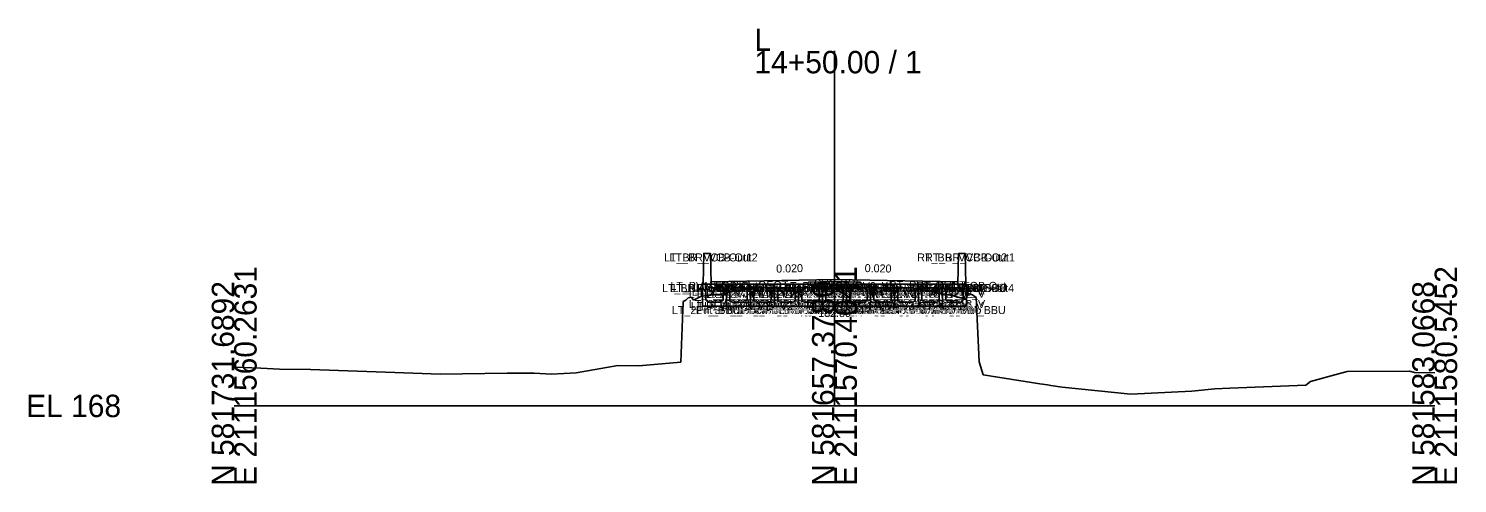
# Model space of a CAD drawing. Extents: x -26 to 3453, y -333 to 9539.
# Drawn here: x -25.7 to 152.8, y 4490.3 to 4547.2 of the extents above; entities that cross this region are included whole.
import ezdxf

# ---------------------------------------------------------------- set-up
doc = ezdxf.new("R2010")
doc.units = 0
for name, color, linetype in [('Default', 7, 'Continuous'), ('Exist Cross Section Cell', 7, 'Continuous'), ('Exist XS Center Line Elevation Label', 7, 'Continuous'), ('Exist XS Ground Line', 7, 'Continuous'), ('Prop CMT Concrete Structures', 7, 'Continuous'), ('Prop CMT Pvmt Course 1', 7, 'Continuous'), ('Prop XS SE Text', 7, 'Continuous'), ('Scratch_Level_0', 7, 'Continuous')]:
    doc.layers.add(name, color=color, linetype=linetype)

msp = doc.modelspace()

# ---------------------------------------------------------------- linework, layer by layer
at = {"layer": 'Exist Cross Section Cell'}
for p, q in [((75, 4500), (75, 4544.39)), ((0, 4500), (75, 4500)), ((75, 4500), (150, 4500))]:
    msp.add_line(p, q, dxfattribs=at)
at = {"layer": 'Exist XS Ground Line'}
for p, q in [((56.41, 4513.23), (56.72, 4513.53)), ((56.72, 4513.53), (57.12, 4513.62)), ((57.12, 4513.62), (57.37, 4513.23)), ((57.37, 4513.23), (58.4, 4513.74)), ((58.4, 4513.74), (61.09, 4514.02)), ((61.09, 4514.02), (63.76, 4514.64)), ((63.76, 4514.64), (64.81, 4514.76)), ((64.81, 4514.76), (74.33, 4514.8)), ((74.33, 4514.8), (74.8, 4514.8)), ((74.8, 4514.8), (84.18, 4514.76)), ((84.18, 4514.76), (84.63, 4514.75)), ((84.63, 4514.75), (89.82, 4513.76)), ((89.82, 4513.76), (91.42, 4513.36)), ((91.42, 4513.36), (91.7, 4514.08)), ((91.7, 4514.08), (92.27, 4513.9)), ((92.27, 4513.9), (92.69, 4513.56)), ((92.69, 4513.56), (93.1, 4505.5)), ((55.82, 4505.48), (56.08, 4513.06)), ((56.08, 4513.06), (56.41, 4513.23)), ((0, 4504.84), (3.33, 4504.71)), ((3.33, 4504.71), (5.64, 4504.61)), ((5.64, 4504.61), (9.53, 4504.57)), ((9.53, 4504.57), (20.08, 4504.18)), ((42.72, 4504.14), (47.94, 4505.05)), ((47.94, 4505.05), (50.56, 4505.02)), ((50.56, 4505.02), (55.82, 4505.48)), ((93.1, 4505.5), (93.6, 4503.88)), ((20.08, 4504.18), (25.72, 4503.96)), ((25.72, 4503.96), (34.11, 4504.08)), ((34.11, 4504.08), (37.46, 4504.08)), ((37.46, 4504.08), (39.64, 4503.96)), ((39.64, 4503.96), (42.72, 4504.14)), ((93.6, 4503.88), (100.66, 4502.78)), ((100.66, 4502.78), (101.63, 4502.63)), ((101.63, 4502.63), (102.05, 4502.54)), ((124.4, 4502.23), (133.89, 4502.6)), ((133.89, 4502.6), (134.47, 4503.06)), ((134.47, 4503.06), (137.99, 4504.03)), ((137.99, 4504.03), (139.05, 4504.31)), ((139.05, 4504.31), (146.86, 4504.33)), ((146.86, 4504.33), (147.47, 4504.2)), ((147.47, 4504.2), (150, 4504.12)), ((102.05, 4502.54), (103.45, 4502.36)), ((103.45, 4502.36), (112.03, 4501.49)), ((112.03, 4501.49), (119.67, 4501.83)), ((119.67, 4501.83), (122.53, 4502.15)), ((122.53, 4502.15), (124.4, 4502.23))]:
    msp.add_line(p, q, dxfattribs=at)
at = {"layer": 'Prop CMT Concrete Structures'}
for points in [[(59.58, 4515.24), (59.5, 4519.07), (58.66, 4519.07), (58.58, 4515.24)], [(90.42, 4515.24), (90.5, 4519.07), (91.33, 4519.07), (91.42, 4515.24)], [(61.5, 4515.24), (58.5, 4515.24)], [(58.5, 4515.24), (58.5, 4512.49)], [(58.58, 4515.24), (59.58, 4515.24)], [(64.5, 4515.24), (61.5, 4515.24)], [(61.5, 4515.24), (61.5, 4512.49)], [(61.5, 4512.49), (61.5, 4515.24)], [(67.5, 4515.24), (64.5, 4515.24)], [(64.5, 4515.24), (64.5, 4512.49)], [(64.5, 4512.49), (64.5, 4515.24)], [(70.5, 4515.24), (67.5, 4515.24)], [(67.5, 4515.24), (67.5, 4512.49)], [(67.5, 4512.49), (67.5, 4515.24)], [(70.5, 4512.49), (70.5, 4515.24)], [(73.51, 4515.24), (70.5, 4515.24)], [(70.5, 4515.24), (70.5, 4512.49)], [(75, 4515.24), (73.51, 4515.24)], [(73.51, 4515.24), (73.51, 4512.49)], [(73.51, 4512.49), (73.51, 4515.24)], [(75, 4515.24), (76.49, 4515.24)], [(76.49, 4515.24), (76.49, 4512.49)], [(76.5, 4515.24), (79.5, 4515.24)], [(76.5, 4512.49), (76.5, 4515.24)], [(79.5, 4515.24), (82.5, 4515.24)], [(79.5, 4512.49), (79.5, 4515.24)], [(79.5, 4515.24), (79.5, 4512.49)], [(82.5, 4515.24), (82.5, 4512.49)], [(82.5, 4515.24), (85.5, 4515.24)], [(82.5, 4512.49), (82.5, 4515.24)], [(85.5, 4515.24), (85.5, 4512.49)], [(85.5, 4515.24), (88.5, 4515.24)], [(85.5, 4512.49), (85.5, 4515.24)], [(88.5, 4515.24), (88.5, 4512.49)], [(88.5, 4515.24), (91.5, 4515.24)], [(88.5, 4512.49), (88.5, 4515.24)], [(91.42, 4515.24), (90.42, 4515.24)], [(91.5, 4515.24), (91.5, 4512.49)], [(58.92, 4514.53), (59.17, 4514.78)], [(58.92, 4513.24), (58.92, 4514.53)], [(59.17, 4514.78), (60.83, 4514.78), (61.08, 4514.53)], [(61.08, 4514.53), (61.08, 4513.24)], [(61.92, 4514.53), (62.17, 4514.78)], [(61.92, 4513.24), (61.92, 4514.53)], [(62.17, 4514.78), (63.83, 4514.78), (64.08, 4514.53)], [(64.08, 4514.53), (64.08, 4513.24)], [(64.92, 4514.53), (65.17, 4514.78)], [(64.92, 4513.24), (64.92, 4514.53)], [(65.17, 4514.78), (66.83, 4514.78), (67.08, 4514.53)], [(67.08, 4514.53), (67.08, 4513.24)], [(67.92, 4514.53), (68.17, 4514.78)], [(67.92, 4513.24), (67.92, 4514.53)], [(68.17, 4514.78), (69.83, 4514.78), (70.08, 4514.53)], [(70.08, 4514.53), (70.08, 4513.24)], [(70.92, 4514.53), (71.17, 4514.78)], [(70.92, 4513.24), (70.92, 4514.53)], [(71.17, 4514.78), (72.84, 4514.78), (73.09, 4514.53)], [(73.09, 4514.53), (73.09, 4513.24)], [(73.93, 4514.53), (74.18, 4514.78), (75, 4514.78)], [(73.93, 4513.24), (73.93, 4514.53)], [(76.07, 4514.53), (75.82, 4514.78), (75, 4514.78)], [(76.07, 4513.24), (76.07, 4514.53)], [(78.83, 4514.78), (77.17, 4514.78), (76.92, 4514.53)], [(76.92, 4514.53), (76.92, 4513.24)], [(79.08, 4514.53), (78.83, 4514.78)], [(79.08, 4513.24), (79.08, 4514.53)], [(81.83, 4514.78), (80.17, 4514.78), (79.92, 4514.53)], [(79.92, 4514.53), (79.92, 4513.24)], [(82.08, 4514.53), (81.83, 4514.78)], [(82.08, 4513.24), (82.08, 4514.53)], [(84.83, 4514.78), (83.17, 4514.78), (82.92, 4514.53)], [(82.92, 4514.53), (82.92, 4513.24)], [(85.08, 4514.53), (84.83, 4514.78)], [(85.08, 4513.24), (85.08, 4514.53)], [(87.83, 4514.78), (86.17, 4514.78), (85.92, 4514.53)], [(85.92, 4514.53), (85.92, 4513.24)], [(88.08, 4514.53), (87.83, 4514.78)], [(88.08, 4513.24), (88.08, 4514.53)], [(90.83, 4514.78), (89.17, 4514.78), (88.92, 4514.53)], [(88.92, 4514.53), (88.92, 4513.24)], [(91.08, 4514.53), (90.83, 4514.78)], [(91.08, 4513.24), (91.08, 4514.53)], [(58.5, 4512.49), (61.5, 4512.49)], [(61.08, 4513.24), (60.83, 4512.99), (59.17, 4512.99), (58.92, 4513.24)], [(61.5, 4512.49), (64.5, 4512.49)], [(64.08, 4513.24), (63.83, 4512.99), (62.17, 4512.99), (61.92, 4513.24)], [(64.5, 4512.49), (67.5, 4512.49)], [(67.08, 4513.24), (66.83, 4512.99), (65.17, 4512.99), (64.92, 4513.24)], [(67.5, 4512.49), (70.5, 4512.49)], [(70.08, 4513.24), (69.83, 4512.99), (68.17, 4512.99), (67.92, 4513.24)], [(70.5, 4512.49), (73.51, 4512.49)], [(73.09, 4513.24), (72.84, 4512.99), (71.17, 4512.99), (70.92, 4513.24)], [(73.51, 4512.49), (75, 4512.49)], [(75, 4512.99), (74.18, 4512.99), (73.93, 4513.24)], [(75, 4512.99), (75.82, 4512.99), (76.07, 4513.24)], [(76.49, 4512.49), (75, 4512.49)], [(79.5, 4512.49), (76.5, 4512.49)], [(76.92, 4513.24), (77.17, 4512.99), (78.83, 4512.99), (79.08, 4513.24)], [(82.5, 4512.49), (79.5, 4512.49)], [(79.92, 4513.24), (80.17, 4512.99), (81.83, 4512.99), (82.08, 4513.24)], [(85.5, 4512.49), (82.5, 4512.49)], [(82.92, 4513.24), (83.17, 4512.99), (84.83, 4512.99), (85.08, 4513.24)], [(88.5, 4512.49), (85.5, 4512.49)], [(85.92, 4513.24), (86.17, 4512.99), (87.83, 4512.99), (88.08, 4513.24)], [(91.5, 4512.49), (88.5, 4512.49)], [(88.92, 4513.24), (89.17, 4512.99), (90.83, 4512.99), (91.08, 4513.24)]]:
    msp.add_lwpolyline(points, dxfattribs=at)
at = {"layer": 'Prop CMT Pvmt Course 1'}
for points in [[(75, 4515.82), (64, 4515.6), (59.57, 4515.51)], [(59.57, 4515.51), (59.58, 4515.24), (61.34, 4515.24), (71.5, 4515.24), (71.76, 4515.49), (75, 4515.57)], [(75, 4515.57), (75, 4515.82)], [(75, 4515.82), (86, 4515.6), (90.42, 4515.51)], [(75, 4515.57), (75, 4515.82)], [(90.42, 4515.51), (90.42, 4515.24), (88.66, 4515.24), (78.5, 4515.24), (78.24, 4515.49), (75, 4515.57)]]:
    msp.add_lwpolyline(points, dxfattribs=at)

# ---------------------------------------------------------------- texts
at = {"layer": 'Default'}
msp.add_text('-', height=0.0001, dxfattribs=at).set_placement((0, 4500))
at = {"layer": 'Exist Cross Section Cell'}
for s, p in [('L', (65, 4544.39)), ('14+50.00 / 1', (65, 4541.59)), ('EL 168', (-26, 4498.6))]:
    msp.add_text(s, height=2.8, dxfattribs=at).set_placement(p)
for s, p in [('E 2111560.2631', (2.8, 4490)), ('E 2111570.4041', (77.8, 4490)), ('E 2111580.5452', (152.8, 4490)), ('N 581731.6892', (0, 4490)), ('N 581657.3780', (75, 4490)), ('N 581583.0668', (150, 4490))]:
    msp.add_text(s, height=2.8, rotation=90, dxfattribs=at).set_placement(p)
at = {"layer": 'Exist XS Center Line Elevation Label'}
msp.add_text('182.80', height=1, dxfattribs=at).set_placement((72.97, 4511.12))
at = {"layer": 'Prop XS SE Text'}
for rotation, p in [(1.1458, (67.73, 4516.67)), (358.8542, (78.77, 4516.74))]:
    msp.add_text('0.020', height=1, rotation=rotation, dxfattribs=at).set_placement(p)
at = {"layer": 'Scratch_Level_0'}
for s, p in [('LT_BR_VCB-Out1', (53.71, 4518.07)), ('LT_BR_VCB-Out2', (54.4, 4518.07)), ('RT_BR_VCB-Out2', (85.35, 4518.07)), ('RT_BR_VCB-Out1', (86.32, 4518.07)), ('LT_BR_VCB-Out4', (53.45, 4514.24)), ('LT_BR_VCB-Out3', (54.47, 4514.24)), ('LT_PV1_FOB-Out', (54.5, 4514.51)), ('LT_1Pnt_BBU', (54.81, 4514.24)), ('LT_4Pnt_BBU', (57.69, 4514.24)), ('LT_PV1_Tent', (57.75, 4514.24)), ('LT_PV1_OEOT', (59.87, 4514.6)), ('LT_4Pnt_BBU1', (60.45, 4514.24)), ('LT_4Pnt_BBU2', (63.31, 4514.24)), ('LT_4Pnt_BBU3', (66.29, 4514.24)), ('LT_PV2_W', (68.7, 4514.49)), ('LT_BR_W', (68.85, 4514.24)), ('LT_4Pnt_BBU5', (69.3, 4514.24)), ('LT_1Pnt_BBU1', (69.58, 4514.24)), ('RT_4Pnt_BBU5', (72.23, 4514.24)), ('PV2_PGL', (72.35, 4514.57)), ('PV1_PGL', (72.47, 4514.82)), ('RT_1Pnt_BBU1', (72.5, 4514.24)), ('BR_PGL', (72.75, 4514.24)), ('RT_PV2_W', (75.12, 4514.49)), ('RT_4Pnt_BBU3', (75.23, 4514.24)), ('RT_BR_W', (75.78, 4514.24)), ('RT_4Pnt_BBU2', (78.25, 4514.24)), ('RT_4Pnt_BBU1', (81.39, 4514.24)), ('RT_PV1_OEOT', (81.81, 4514.6)), ('RT_4Pnt_BBU', (84.63, 4514.24)), ('RT_PV1_Tent', (85.01, 4514.24)), ('RT_BR_VCB-Out3', (85.25, 4514.24)), ('RT_PV1_FOB-Out', (85.29, 4514.51)), ('RT_BR_VCB-Out4', (86.23, 4514.24)), ('RT_1Pnt_BBU', (87.75, 4514.24)), ('LT_2_V', (56.81, 4513.53)), ('LT_1_V', (57.18, 4513.78)), ('LT_8_V', (58.73, 4513.78)), ('LT_7_V', (58.98, 4513.53)), ('LT_2_V1', (59.64, 4513.53)), ('LT_1_V1', (60.01, 4513.78)), ('LT_8_V1', (61.56, 4513.78)), ('LT_7_V1', (61.81, 4513.53)), ('LT_2_V2', (62.49, 4513.53)), ('LT_1_V2', (62.86, 4513.78)), ('LT_8_V2', (64.41, 4513.78)), ('LT_7_V2', (64.66, 4513.53)), ('LT_2_V3', (65.48, 4513.53)), ('LT_1_V3', (65.85, 4513.78)), ('LT_8_V3', (67.39, 4513.78)), ('LT_7_V3', (67.64, 4513.53)), ('LT_2_V6', (68.47, 4513.53)), ('LT_1_V6', (68.83, 4513.78)), ('LT_8_V5', (70.4, 4513.78)), ('LT_7_V5', (70.65, 4513.53)), ('LT_2_V4', (71.47, 4513.53)), ('LT_1_V4', (71.84, 4513.78)), ('RT_1_V4', (73.43, 4513.78)), ('6_V4', (73.51, 4513.78)), ('RT_2_V4', (73.56, 4513.53)), ('RT_7_V5', (74.41, 4513.53)), ('RT_8_V5', (74.66, 4513.78)), ('RT_1_V6', (76.44, 4513.78)), ('RT_2_V6', (76.57, 4513.53)), ('RT_7_V3', (77.42, 4513.53)), ('RT_8_V3', (77.67, 4513.78)), ('RT_1_V3', (79.45, 4513.78)), ('RT_2_V3', (79.59, 4513.53)), ('RT_7_V2', (80.43, 4513.53)), ('RT_8_V2', (80.68, 4513.78)), ('RT_1_V2', (82.47, 4513.78)), ('RT_2_V2', (82.6, 4513.53)), ('RT_7_V1', (83.58, 4513.53)), ('RT_8_V1', (83.83, 4513.78)), ('RT_1_V1', (85.62, 4513.78)), ('RT_2_V1', (85.75, 4513.53)), ('RT_7_V', (86.76, 4513.53)), ('RT_8_V', (87.01, 4513.78)), ('RT_1_V', (88.79, 4513.78)), ('RT_2_V', (88.92, 4513.53)), ('LT_2Pnt_BBU', (54.69, 4511.49)), ('LT_3_V', (56.81, 4512.24)), ('LT_4_V', (57.06, 4511.99)), ('LT_3Pnt_BBU', (57.69, 4511.49)), ('LT_5_V', (58.73, 4511.99)), ('LT_6_V', (58.98, 4512.24)), ('LT_3_V1', (59.64, 4512.24)), ('LT_4_V1', (59.89, 4511.99)), ('LT_3Pnt_BBU1', (60.45, 4511.49)), ('LT_5_V1', (61.56, 4511.99)), ('LT_6_V1', (61.81, 4512.24)), ('LT_3_V2', (62.49, 4512.24)), ('LT_4_V2', (62.74, 4511.99)), ('LT_3Pnt_BBU2', (63.31, 4511.49)), ('LT_5_V2', (64.41, 4511.99)), ('LT_6_V2', (64.66, 4512.24)), ('LT_3_V3', (65.48, 4512.24)), ('LT_4_V3', (65.73, 4511.99)), ('LT_3Pnt_BBU3', (66.29, 4511.49)), ('LT_5_V3', (67.39, 4511.99)), ('LT_6_V3', (67.64, 4512.24)), ('LT_3_V6', (68.47, 4512.24)), ('LT_4_V6', (68.72, 4511.99)), ('LT_3Pnt_BBU6', (69.29, 4511.49)), ('LT_2Pnt_BBU1', (69.46, 4511.49)), ('LT_5_V6', (70.39, 4511.99)), ('LT_6_V6', (70.64, 4512.24)), ('LT_3_V4', (71.47, 4512.24)), ('3Pnt_BBU4', (71.74, 4511.49)), ('LT_4_V4', (71.72, 4511.99)), ('RT_3Pnt_BBU6', (72.22, 4511.49)), ('RT_2Pnt_BBU1', (72.38, 4511.49)), ('RT_4_V4', (73.31, 4511.99)), ('5_V4', (73.51, 4511.99)), ('RT_3_V4', (73.56, 4512.24)), ('RT_6_V6', (74.41, 4512.24)), ('RT_5_V6', (74.66, 4511.99)), ('RT_3Pnt_BBU3', (75.23, 4511.49)), ('RT_4_V6', (76.32, 4511.99)), ('RT_3_V6', (76.57, 4512.24)), ('RT_6_V3', (77.42, 4512.24)), ('RT_5_V3', (77.67, 4511.99)), ('RT_3Pnt_BBU2', (78.25, 4511.49)), ('RT_4_V3', (79.34, 4511.99)), ('RT_3_V3', (79.59, 4512.24)), ('RT_6_V2', (80.43, 4512.24)), ('RT_5_V2', (80.68, 4511.99)), ('RT_3Pnt_BBU1', (81.39, 4511.49)), ('RT_4_V2', (82.35, 4511.99)), ('RT_3_V2', (82.6, 4512.24)), ('RT_6_V1', (83.58, 4512.24)), ('RT_5_V1', (83.83, 4511.99)), ('RT_3Pnt_BBU', (84.63, 4511.49)), ('RT_4_V1', (85.5, 4511.99)), ('RT_3_V1', (85.75, 4512.24)), ('RT_6_V', (86.76, 4512.24)), ('RT_5_V', (87.01, 4511.99)), ('RT_2Pnt_BBU', (87.63, 4511.49)), ('RT_4_V', (88.67, 4511.99)), ('RT_3_V', (88.92, 4512.24))]:
    msp.add_text(s, height=1, dxfattribs=at).set_placement(p)

doc.saveas('drawing.dxf')
